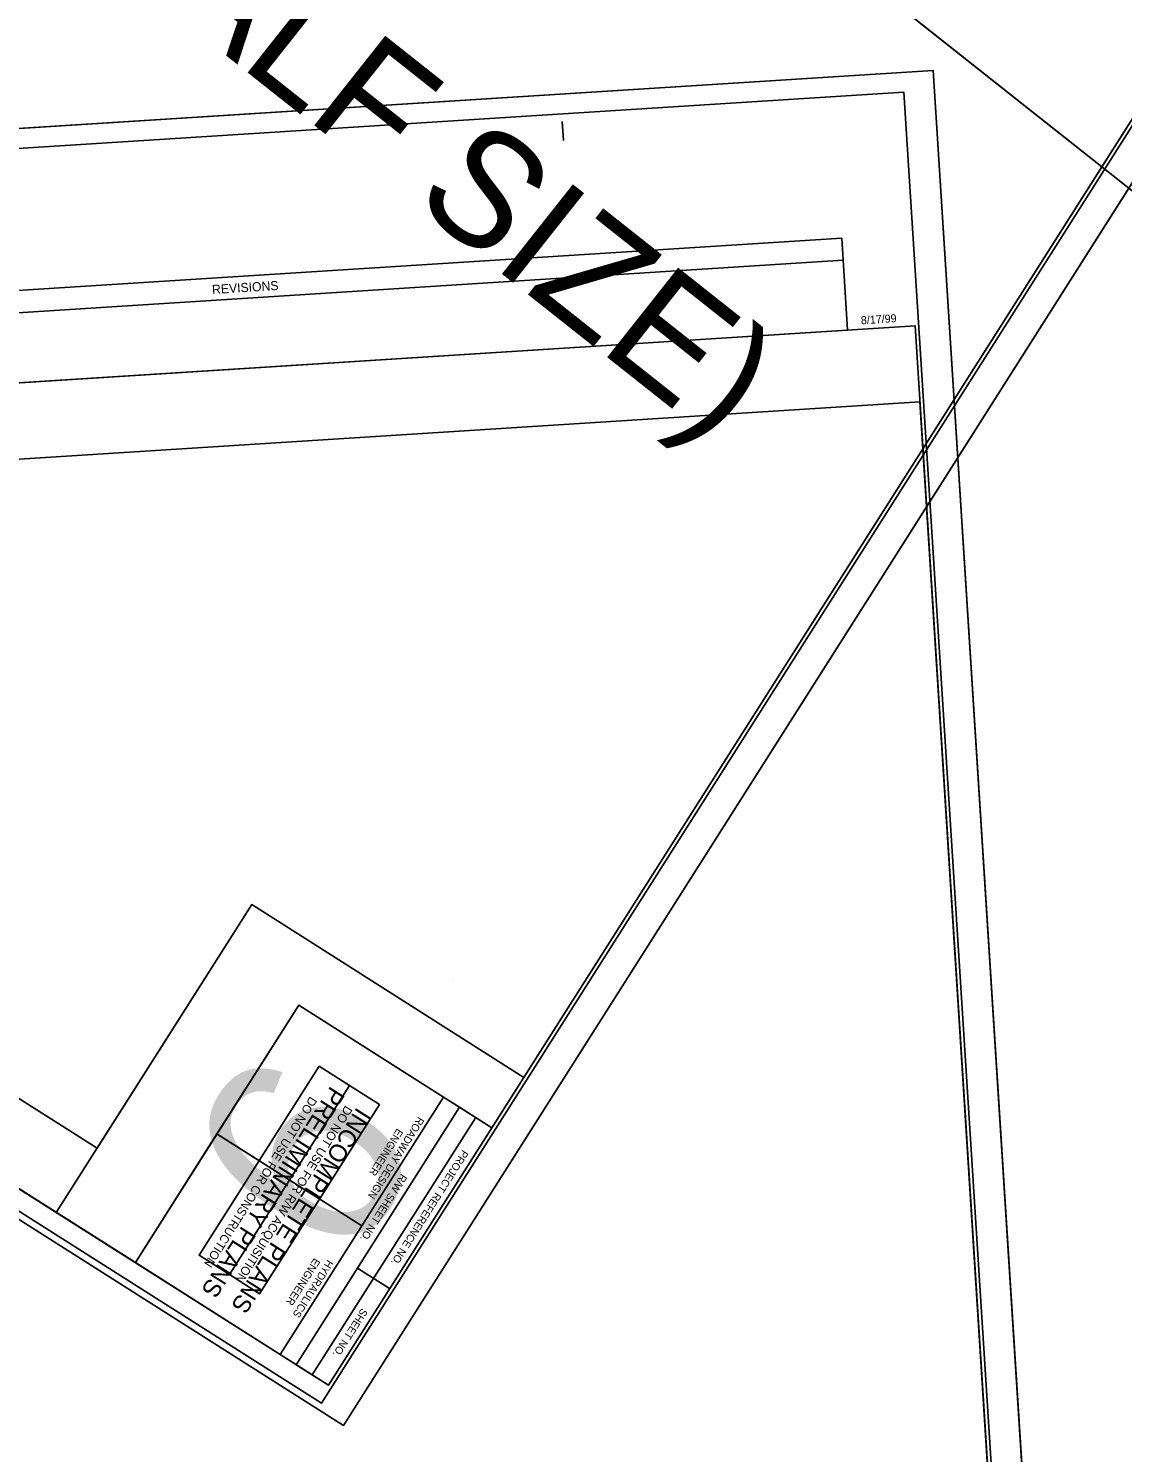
# Model space of a CAD drawing. Extents: x 1778994 to 1784559, y 810461 to 816654.
# Drawn here: x 1780917 to 1781635, y 811304 to 812239 of the extents above; entities that cross this region are included whole.
import ezdxf

# ---------------------------------------------------------------- set-up
doc = ezdxf.new("R2010")
doc.units = 0
for name, color, linetype in [('Sheet Block Revision CELL', 7, 'Continuous'), ('Sheet Clip Boundary CELL', 7, 'Continuous'), ('Sheet Cutting Line CELL', 7, 'Continuous'), ('Sheet Detail CELL', 7, 'Continuous'), ('Sheet Layout Plan Border', 7, 'Continuous'), ('Sheet North Arrow Point CELL', 7, 'Continuous'), ('Sheet Plan CELL', 7, 'Continuous'), ('Sheet Plan Layout CELL', 7, 'Continuous'), ('Sheet Plot Border Inside CELL', 7, 'Continuous'), ('Sheet Plot Border Outside CELL', 7, 'Continuous'), ('Sheet Sticker Incomplete CELL', 7, 'Continuous'), ('Sheet Sticker Preliminary CELL', 7, 'Continuous')]:
    doc.layers.add(name, color=color, linetype=linetype)

msp = doc.modelspace()

# ---------------------------------------------------------------- linework, layer by layer
at = {"layer": 'Sheet Block Revision CELL'}
msp.add_line((1780662.92, 812036.32), (1781451.96, 812086.48), dxfattribs=at)
msp.add_lwpolyline([(1780661.97, 812050.84), (1781451.03, 812100.99), (1781454.89, 812040.57), (1780665.83, 811990.43)], close=True, dxfattribs=at)
at = {"layer": 'Sheet Clip Boundary CELL'}
for points in [[(1781004.66, 813135.18), (1780254.51, 811953.1), (1780962.49, 811503.81), (1781063.9, 811663.61), (1781242.47, 811550.29), (1781891.21, 812572.57)], [(1780454.44, 811926.9), (1780543.23, 810529.71), (1781380.05, 810582.89), (1781368.05, 810771.77), (1781579.11, 810785.19), (1781502.32, 811993.5)]]:
    msp.add_lwpolyline(points, close=True, dxfattribs=at)
at = {"layer": 'Sheet Cutting Line CELL'}
for p, q in [((1780384.09, 813127.55), (1783024.7, 811036.95)), ((1781124.14, 811321.87), (1782026.2, 812743.3)), ((1781511.04, 812210.98), (1780418.24, 812141.53)), ((1781617.81, 810530.87), (1781511.04, 812210.98))]:
    msp.add_line(p, q, dxfattribs=at)
at = {"layer": 'Sheet Layout Plan Border'}
for points in [[(1781004.66, 813135.18), (1780254.51, 811953.1), (1780962.49, 811503.81), (1781063.9, 811663.61), (1781242.47, 811550.29), (1781891.21, 812572.57)], [(1780454.44, 811926.9), (1780543.23, 810529.71), (1781380.05, 810582.89), (1781368.05, 810771.77), (1781579.11, 810785.19), (1781502.32, 811993.5)]]:
    msp.add_lwpolyline(points, close=True, dxfattribs=at)
at = {"layer": 'Sheet North Arrow Point CELL'}
msp.add_line((1781196.34, 811613.73), (1781196.34, 811613.73), dxfattribs=at)
at = {"layer": 'Sheet Plan CELL'}
for p, q in [((1781267.66, 812177.49), (1781268.48, 812165)), ((1781499.15, 812043.4), (1781499.15, 812043.4)), ((1781200.28, 811530.62), (1781189.74, 811537.31)), ((1781200.28, 811530.62), (1781093.12, 811361.71)), ((1781200.28, 811530.62), (1781093.12, 811361.71)), ((1781210.88, 811523.91), (1781103.67, 811355.01)), ((1781136.13, 811452.83), (1781041.17, 811513.08)), ((1781154.42, 811411.66), (1781133.28, 811425.02))]:
    msp.add_line(p, q, dxfattribs=at)
for points in [[(1781114.25, 811348.25), (1781918, 812614.78), (1781031.45, 813177.39), (1780227.72, 811910.89)], [(1781031.45, 813177.39), (1781917.99, 812614.82), (1781221.47, 811517.18), (1781094.76, 811597.57), (1780987.56, 811428.68), (1780227.72, 811910.89)], [(1780451.27, 811976.8), (1781499.13, 812043.42), (1781581.61, 810746.05), (1781431.85, 810736.52), (1781444.53, 810536.89), (1780546.4, 810479.81)], [(1781594.29, 810546.38), (1781499.15, 812043.4), (1780451.27, 811976.8), (1780546.4, 810479.81)], [(1781189.74, 811537.31), (1781136.13, 811452.83), (1781041.13, 811513.12), (1781094.76, 811597.57)], [(1781221.47, 811517.18), (1781114.25, 811348.25), (1781093.12, 811361.71), (1781200.28, 811530.62)], [(1781136.13, 811452.83), (1781082.57, 811368.4), (1780987.56, 811428.68), (1781041.13, 811513.12)]]:
    msp.add_lwpolyline(points, close=True, dxfattribs=at)
at = {"layer": 'Sheet Plan Layout CELL'}
for points in [[(1781917.99, 812614.82), (1781031.45, 813177.39), (1780227.72, 811910.9), (1780935.71, 811461.6), (1781063.9, 811663.61), (1781242.47, 811550.29)], [(1781499.13, 812043.42), (1780451.27, 811976.8), (1780546.4, 810479.82), (1781383.23, 810533), (1781368.05, 810771.77), (1781579.11, 810785.19)], [(1781063.9, 811663.61), (1780935.69, 811461.58), (1781114.24, 811348.24), (1781242.47, 811550.29)]]:
    msp.add_lwpolyline(points, close=True, dxfattribs=at)
at = {"layer": 'Sheet Plot Border Inside CELL'}
for points in [[(1781111.57, 813308.33), (1780218.91, 811901.68), (1781109.67, 811336.39), (1782002.34, 812743.04)], [(1780439.02, 812129.82), (1780544.7, 810467.19), (1781597.56, 810534.09), (1781491.9, 812196.73)]]:
    msp.add_lwpolyline(points, close=True, dxfattribs=at)
at = {"layer": 'Sheet Plot Border Outside CELL'}
for points in [[(1784390.27, 812761.78), (1781749.66, 814852.38), (1780384.09, 813127.55), (1783024.7, 811036.95)], [(1781101.65, 813330.03), (1780199.6, 811908.59), (1781124.14, 811321.87), (1782026.2, 812743.3)], [(1780418.24, 812141.53), (1780525.01, 810461.42), (1781617.81, 810530.87), (1781511.04, 812210.98)]]:
    msp.add_lwpolyline(points, close=True, dxfattribs=at)
at = {"layer": 'Sheet Sticker Incomplete CELL'}
msp.add_lwpolyline([(1781128.02, 811545.03), (1781147.86, 811532.44), (1781069.1, 811408.32), (1781049.25, 811420.92)], close=True, dxfattribs=at)
at = {"layer": 'Sheet Sticker Preliminary CELL'}
msp.add_lwpolyline([(1781108.18, 811557.62), (1781128.02, 811545.03), (1781049.25, 811420.92), (1781029.41, 811433.51)], close=True, dxfattribs=at)

# ---------------------------------------------------------------- texts
at = {"layer": 'Sheet Block Revision CELL'}
msp.add_text('REVISIONS', height=6, rotation=3.6363, dxfattribs=at).set_placement((1781038.05, 812064.22))
at = {"layer": 'Sheet Detail CELL'}
msp.add_text('TO PLOT 34"(HALF SIZE)', height=75, rotation=321.63093, dxfattribs=at).set_placement((1780445.73, 812696.88))
at = {"layer": 'Sheet Plan CELL'}
for s, height, rotation, p in [('8/17/99', 5.25, 3.63631, (1781463.79, 812044.38)), ('ROADWAY DESIGN', 5.0001, 237.6004, (1781173.19, 811524.86)), ('ENGINEER', 5, 237.6004, (1781159.34, 811517.09)), ('PROJECT REFERENCE NO.', 5.0001, 237.6004, (1781202.2, 811503.11)), ('R/W SHEET NO.', 5.0001, 237.6004, (1781161.98, 811487.41)), ('ENGINEER', 5, 237.6004, (1781104.93, 811432.1)), ('HYDRAULICS', 5, 237.6004, (1781113.67, 811431.01)), ('SHEET NO.', 5, 237.6004, (1781136.12, 811399.18))]:
    msp.add_text(s, height=height, rotation=rotation, dxfattribs=at).set_placement(p)
at = {"layer": 'Sheet Plan Layout CELL'}
msp.add_text('9', height=131.25, rotation=237.60039, dxfattribs=at).set_placement((1781068.27, 811576.4))
at = {"layer": 'Sheet Sticker Incomplete CELL'}
for s, height, p in [('INCOMPLETE PLANS', 11.52, (1781133.1, 811531.21)), ('DO NOT USE FOR R/W ACQUISITION', 5.76, (1781125.49, 811532.19))]:
    msp.add_text(s, height=height, rotation=237.60039, dxfattribs=at).set_placement(p)
at = {"layer": 'Sheet Sticker Preliminary CELL'}
for s, height, p in [('PRELIMINARY PLANS', 11.52, (1781115.8, 811545.09)), ('DO NOT USE FOR CONSTRUCTION', 5.76, (1781102.28, 811538.15))]:
    msp.add_text(s, height=height, rotation=237.60039, dxfattribs=at).set_placement(p)

doc.saveas('drawing.dxf')
